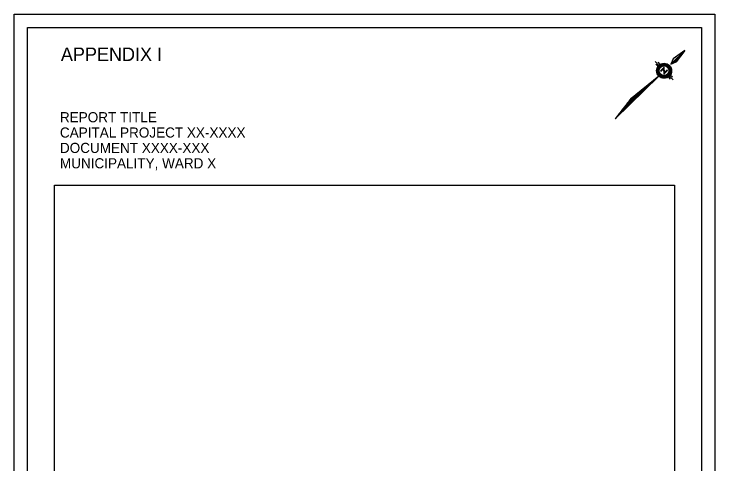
# Model space of a CAD drawing. Extents: x 613702 to 613806, y 4819213 to 4819347.
# Drawn here: x 613702.4 to 613806.4, y 4819279.8 to 4819346.5 of the extents above; entities that cross this region are included whole.
import ezdxf

# ---------------------------------------------------------------- set-up
doc = ezdxf.new("R2010")
doc.units = 0
for name, color, linetype in [('G-ANNO-SYMB', 7, 'Continuous'), ('G-ANNO-TEXT', 7, 'Continuous'), ('G-TTLB-OTLN', 7, 'Continuous'), ('G-TTLB-OTLN-PB', 7, 'Continuous')]:
    doc.layers.add(name, color=color, linetype=linetype)

msp = doc.modelspace()

# ---------------------------------------------------------------- linework, layer by layer
at = {"layer": 'G-ANNO-SYMB'}
for p, q in [((613801.88, 4819341.1), (613799.83, 4819339.09)), ((613801.88, 4819341.1), (613800.18, 4819339.89)), ((613801.88, 4819341.1), (613800.64, 4819339.43)), ((613799.86, 4819339.1), (613801.79, 4819340.98)), ((613799.93, 4819339.13), (613801.69, 4819340.84)), ((613800, 4819339.16), (613801.58, 4819340.7)), ((613800.07, 4819339.19), (613801.48, 4819340.55)), ((613800.14, 4819339.22), (613801.37, 4819340.41)), ((613800.21, 4819339.25), (613801.27, 4819340.27)), ((613800.28, 4819339.28), (613801.16, 4819340.13)), ((613800.35, 4819339.31), (613801.05, 4819339.99)), ((613798.05, 4819338.91), (613797.51, 4819339.46)), ((613797.61, 4819339.09), (613797.92, 4819338.77)), ((613797.88, 4819339.36), (613798.2, 4819339.04)), ((613797.91, 4819338.43), (613798.54, 4819339.04)), ((613797.94, 4819338.49), (613798.48, 4819339.02)), ((613797.97, 4819338.57), (613798.4, 4819338.99)), ((613798.03, 4819338.66), (613798.31, 4819338.93)), ((613798.27, 4819338.74), (613798.6, 4819339.06)), ((613798.27, 4819338.74), (613798.6, 4819339.06)), ((613798.42, 4819338.85), (613798.65, 4819339.07)), ((613798.5, 4819338.89), (613798.7, 4819339.08)), ((613798.57, 4819338.91), (613798.75, 4819339.08)), ((613798.63, 4819338.93), (613798.79, 4819339.09)), ((613798.68, 4819338.94), (613798.83, 4819339.09)), ((613798.73, 4819338.95), (613798.87, 4819339.09)), ((613798.77, 4819338.95), (613798.91, 4819339.08)), ((613798.82, 4819338.95), (613798.95, 4819339.08)), ((613798.86, 4819338.95), (613798.98, 4819339.08)), ((613798.9, 4819338.95), (613799.02, 4819339.07)), ((613798.93, 4819338.95), (613799.05, 4819339.06)), ((613798.97, 4819338.94), (613799.08, 4819339.06)), ((613799, 4819338.94), (613799.11, 4819339.05)), ((613799.03, 4819338.93), (613799.14, 4819339.04)), ((613799.07, 4819338.92), (613799.17, 4819339.03)), ((613799.1, 4819338.91), (613799.2, 4819339.02)), ((613799.13, 4819338.9), (613799.23, 4819339)), ((613799.16, 4819338.89), (613799.26, 4819338.99)), ((613799.18, 4819338.88), (613799.28, 4819338.98)), ((613799.21, 4819338.87), (613799.31, 4819338.96)), ((613799.24, 4819338.85), (613799.34, 4819338.95)), ((613799.26, 4819338.84), (613799.36, 4819338.93)), ((613799.29, 4819338.82), (613799.38, 4819338.92)), ((613800.18, 4819339.89), (613799.83, 4819339.09)), ((613800.64, 4819339.43), (613799.83, 4819339.09)), ((613800.42, 4819339.34), (613800.95, 4819339.85)), ((613800.5, 4819339.37), (613800.84, 4819339.7)), ((613800.57, 4819339.4), (613800.74, 4819339.56)), ((613797.86, 4819338.18), (613798.02, 4819338.34)), ((613797.86, 4819338.14), (613798.01, 4819338.29)), ((613797.86, 4819338.1), (613798, 4819338.24)), ((613797.86, 4819338.07), (613797.99, 4819338.2)), ((613797.86, 4819338.03), (613797.99, 4819338.15)), ((613797.87, 4819338.27), (613798.07, 4819338.46)), ((613797.87, 4819338.23), (613798.04, 4819338.4)), ((613797.87, 4819337.99), (613797.99, 4819338.11)), ((613797.87, 4819337.96), (613797.99, 4819338.08)), ((613797.88, 4819338.32), (613798.11, 4819338.54)), ((613797.88, 4819337.92), (613797.99, 4819338.04)), ((613797.88, 4819337.89), (613798, 4819338)), ((613797.89, 4819338.37), (613798.23, 4819338.7)), ((613797.89, 4819337.86), (613798, 4819337.97)), ((613797.9, 4819337.83), (613798.01, 4819337.94)), ((613797.91, 4819337.8), (613798.02, 4819337.9)), ((613798.86, 4819338.65), (613798.31, 4819338.11)), ((613798.31, 4819338.11), (613798.37, 4819338.04)), ((613798.37, 4819338.04), (613798.75, 4819338.41)), ((613798.75, 4819338.41), (613798.78, 4819337.61)), ((613798.78, 4819337.61), (613799.34, 4819338.15)), ((613798.89, 4819337.85), (613798.86, 4819338.65)), ((613799.27, 4819338.22), (613798.89, 4819337.85)), ((613799.34, 4819338.15), (613799.27, 4819338.22)), ((613799.31, 4819338.81), (613799.41, 4819338.9)), ((613799.34, 4819338.79), (613799.43, 4819338.88)), ((613799.36, 4819338.77), (613799.45, 4819338.87)), ((613799.38, 4819338.76), (613799.47, 4819338.85)), ((613799.4, 4819338.74), (613799.5, 4819338.83)), ((613799.42, 4819338.72), (613799.52, 4819338.81)), ((613799.44, 4819338.7), (613799.54, 4819338.79)), ((613799.46, 4819338.68), (613799.56, 4819338.77)), ((613799.48, 4819338.66), (613799.57, 4819338.75)), ((613799.5, 4819338.63), (613799.59, 4819338.73)), ((613799.51, 4819338.61), (613799.61, 4819338.7)), ((613799.53, 4819338.59), (613799.63, 4819338.68)), ((613799.55, 4819338.56), (613799.64, 4819338.66)), ((613799.55, 4819337.67), (613799.79, 4819337.89)), ((613799.56, 4819338.54), (613799.66, 4819338.63)), ((613799.58, 4819338.51), (613799.67, 4819338.61)), ((613799.59, 4819338.49), (613799.69, 4819338.58)), ((613799.6, 4819338.46), (613799.7, 4819338.56)), ((613799.6, 4819337.75), (613799.8, 4819337.94)), ((613799.61, 4819338.43), (613799.72, 4819338.53)), ((613799.63, 4819338.41), (613799.73, 4819338.5)), ((613799.63, 4819337.82), (613799.8, 4819337.99)), ((613799.64, 4819338.38), (613799.74, 4819338.48)), ((613799.64, 4819337.87), (613799.81, 4819338.03)), ((613799.65, 4819338.35), (613799.75, 4819338.45)), ((613799.65, 4819338.31), (613799.76, 4819338.42)), ((613799.66, 4819338.28), (613799.77, 4819338.39)), ((613799.66, 4819337.93), (613799.81, 4819338.07)), ((613799.67, 4819338.25), (613799.78, 4819338.36)), ((613799.67, 4819338.21), (613799.79, 4819338.33)), ((613799.67, 4819338.02), (613799.81, 4819338.15)), ((613799.67, 4819337.97), (613799.81, 4819338.11)), ((613799.68, 4819338.18), (613799.79, 4819338.29)), ((613799.68, 4819338.14), (613799.8, 4819338.26)), ((613799.68, 4819338.1), (613799.8, 4819338.22)), ((613799.68, 4819338.06), (613799.81, 4819338.19)), ((613798.03, 4819337.32), (613791.55, 4819330.97)), ((613791.77, 4819331.25), (613798, 4819337.3)), ((613791.89, 4819331.41), (613797.75, 4819337.1)), ((613792.01, 4819331.56), (613797.5, 4819336.89)), ((613798.03, 4819337.32), (613793.82, 4819333.91)), ((613797.92, 4819337.77), (613798.02, 4819337.87)), ((613797.93, 4819337.74), (613798.03, 4819337.84)), ((613797.94, 4819337.71), (613798.04, 4819337.81)), ((613797.96, 4819337.69), (613798.06, 4819337.78)), ((613797.97, 4819337.66), (613798.07, 4819337.76)), ((613797.98, 4819337.63), (613798.08, 4819337.73)), ((613798, 4819337.61), (613798.09, 4819337.7)), ((613798.01, 4819337.58), (613798.11, 4819337.68)), ((613798.03, 4819337.56), (613798.12, 4819337.65)), ((613798.04, 4819337.54), (613798.14, 4819337.63)), ((613798.06, 4819337.51), (613798.16, 4819337.61)), ((613798.08, 4819337.49), (613798.17, 4819337.58)), ((613798.1, 4819337.47), (613798.19, 4819337.56)), ((613798.12, 4819337.45), (613798.21, 4819337.54)), ((613798.14, 4819337.43), (613798.23, 4819337.52)), ((613798.16, 4819337.41), (613798.25, 4819337.5)), ((613798.18, 4819337.39), (613798.27, 4819337.48)), ((613798.2, 4819337.37), (613798.29, 4819337.46)), ((613798.22, 4819337.35), (613798.31, 4819337.45)), ((613798.24, 4819337.34), (613798.34, 4819337.43)), ((613798.26, 4819337.32), (613798.36, 4819337.41)), ((613798.29, 4819337.3), (613798.38, 4819337.4)), ((613798.31, 4819337.29), (613798.41, 4819337.38)), ((613798.34, 4819337.27), (613798.43, 4819337.37)), ((613798.36, 4819337.26), (613798.46, 4819337.35)), ((613798.39, 4819337.24), (613798.49, 4819337.34)), ((613798.41, 4819337.23), (613798.52, 4819337.33)), ((613798.44, 4819337.22), (613798.55, 4819337.32)), ((613798.47, 4819337.21), (613798.58, 4819337.31)), ((613798.5, 4819337.19), (613798.61, 4819337.3)), ((613798.53, 4819337.18), (613798.64, 4819337.29)), ((613798.56, 4819337.17), (613798.67, 4819337.28)), ((613798.59, 4819337.17), (613798.71, 4819337.28)), ((613798.62, 4819337.16), (613798.74, 4819337.27)), ((613798.66, 4819337.15), (613798.78, 4819337.27)), ((613798.69, 4819337.15), (613798.82, 4819337.27)), ((613798.73, 4819337.14), (613798.86, 4819337.27)), ((613798.76, 4819337.14), (613798.9, 4819337.27)), ((613798.8, 4819337.14), (613798.95, 4819337.27)), ((613798.84, 4819337.13), (613798.99, 4819337.28)), ((613798.89, 4819337.14), (613799.05, 4819337.29)), ((613798.93, 4819337.14), (613799.11, 4819337.31)), ((613798.98, 4819337.14), (613799.17, 4819337.34)), ((613799.02, 4819337.15), (613799.26, 4819337.38)), ((613799.08, 4819337.17), (613799.77, 4819337.84)), ((613799.13, 4819337.18), (613799.75, 4819337.78)), ((613799.2, 4819337.21), (613799.73, 4819337.72)), ((613799.2, 4819337.21), (613799.73, 4819337.72)), ((613799.28, 4819337.24), (613799.69, 4819337.64)), ((613799.38, 4819337.3), (613799.63, 4819337.54)), ((613799.78, 4819336.87), (613799.47, 4819337.19)), ((613799.62, 4819337.31), (613800.16, 4819336.76)), ((613800.06, 4819337.14), (613799.75, 4819337.46)), ((613792.13, 4819331.72), (613797.26, 4819336.69)), ((613792.26, 4819331.88), (613797.01, 4819336.49)), ((613792.38, 4819332.04), (613796.76, 4819336.29)), ((613792.5, 4819332.2), (613796.51, 4819336.09)), ((613792.62, 4819332.35), (613796.26, 4819335.89)), ((613792.74, 4819332.51), (613796.02, 4819335.69)), ((613792.87, 4819332.67), (613795.77, 4819335.49)), ((613792.99, 4819332.83), (613795.52, 4819335.29)), ((613793.11, 4819332.98), (613795.27, 4819335.08)), ((613793.23, 4819333.14), (613795.03, 4819334.88)), ((613793.82, 4819333.91), (613791.55, 4819330.97)), ((613791.65, 4819331.09), (613794.57, 4819333.93)), ((613793.35, 4819333.3), (613794.78, 4819334.68)), ((613793.48, 4819333.46), (613794.53, 4819334.48)), ((613793.6, 4819333.62), (613794.28, 4819334.28)), ((613793.72, 4819333.77), (613794.04, 4819334.08))]:
    msp.add_line(p, q, dxfattribs=at)
for points in [[(613799.83, 4819339.09), (613800.64, 4819339.43), (613801.88, 4819341.1)], [(613791.55, 4819330.97), (613798.03, 4819337.32), (613793.82, 4819333.91)]]:
    msp.add_lwpolyline(points, close=True, dxfattribs=at)
for radius in [1.12, 0.976, 0.844, 0.723]:
    msp.add_circle((613798.83, 4819338.11), radius, dxfattribs=at)
at = {"layer": 'G-TTLB-OTLN'}
for points in [[(613704.38, 4819344.52), (613804.38, 4819344.52), (613804.38, 4819215.11), (613704.38, 4819215.11)], [(613708.38, 4819321.14), (613800.38, 4819321.14), (613800.38, 4819226.02), (613708.38, 4819226.02)]]:
    msp.add_lwpolyline(points, close=True, dxfattribs=at)
at = {"layer": 'G-TTLB-OTLN-PB'}
msp.add_lwpolyline([(613702.38, 4819346.52), (613806.38, 4819346.52), (613806.38, 4819213.11), (613702.38, 4819213.11)], close=True, dxfattribs=at)

# ---------------------------------------------------------------- texts
at = {"layer": 'G-ANNO-TEXT'}
for s, height, p in [('APPENDIX I', 2, (613709.33, 4819339.55)), ('REPORT TITLE', 1.5, (613709.19, 4819330.47)), ('CAPITAL PROJECT XX-XXXX', 1.5, (613709.19, 4819328.2)), ('DOCUMENT XXXX-XXX', 1.5, (613709.19, 4819325.92)), ('MUNICIPALITY, WARD X', 1.5, (613709.19, 4819323.64))]:
    msp.add_text(s, height=height, dxfattribs=at).set_placement(p)

doc.saveas('drawing.dxf')
